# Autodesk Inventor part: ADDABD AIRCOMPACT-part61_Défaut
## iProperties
Shininess: 64.0
Length Units: 11269
Angle Units: 11279
Time Units: 11290
Mass Units: 11283
Length Display Precision: 3
Angle Display Precision: 2
Compacted: True
Part Number: ADDABD AIRCOMPACT-part61_Défaut
Document SubType Name: Modeling
Created: 2006-01
Material: Par défaut
Designer: riri
Density: 0.0
Volumn: 0.0
Area: 0.0
PropertySet Name: Model Information
Control State: 0
Master: False
Checked Out: False
Author: riri
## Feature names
1. Base1
